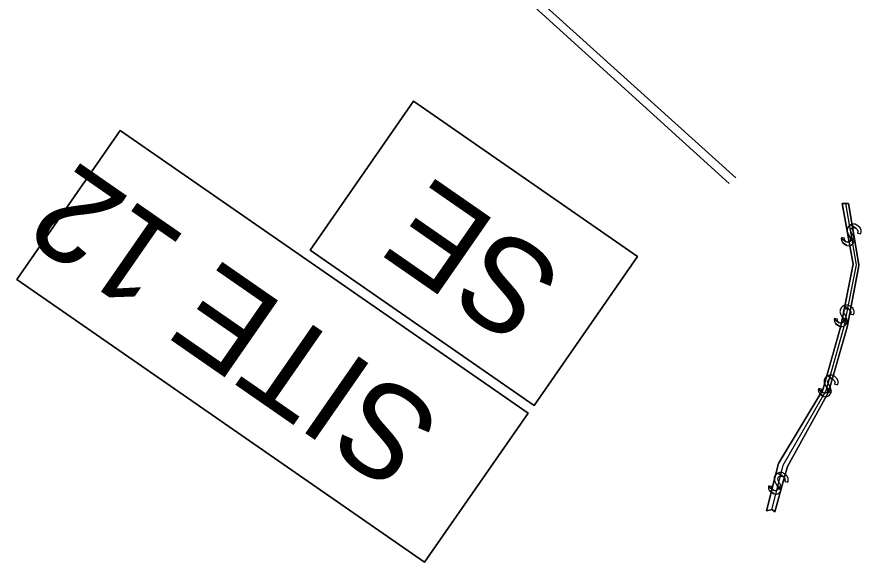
# Model space of a CAD drawing. Extents: x 474218 to 481634, y 484357 to 504997.
# Drawn here: x 478768.1 to 478903.4, y 494014.7 to 494102.1 of the extents above; entities that cross this region are included whole.
import ezdxf

# ---------------------------------------------------------------- set-up
doc = ezdxf.new("R2010")
doc.units = 0
for name, color, linetype in [('Exist Hydro Jurisdictional Stream or Body of Water', 7, 'Continuous'), ('Old_Level_29', 7, 'Continuous'), ('Prop Earthen Structure Impacts In Surface Waters Hatching CELL', 7, 'Continuous'), ('Prop Grid Mask', 7, 'Continuous'), ('Scratch_Level_4', 7, 'Continuous')]:
    doc.layers.add(name, color=color, linetype=linetype)

msp = doc.modelspace()

# ---------------------------------------------------------------- linework, layer by layer
at = {"layer": 'Exist Hydro Jurisdictional Stream or Body of Water'}
msp.add_lwpolyline([(478851.01, 494039.79), (478815.08, 494064.72), (478831.66, 494088.62), (478867.58, 494063.69)], close=True, dxfattribs=at)
at = {"layer": 'Old_Level_29'}
msp.add_lwpolyline([(478833.44, 494014.68), (478768.06, 494060.03), (478784.64, 494083.93), (478850.02, 494038.58)], close=True, dxfattribs=at)
at = {"layer": 'Prop Earthen Structure Impacts In Surface Waters Hatching CELL'}
msp.add_lwpolyline([(478891.05, 494028.01), (478891.61, 494030.01), (478896.76, 494039.31), (478898.21, 494041.94), (478901.18, 494052.35), (478902.99, 494061.94), (478903.07, 494062.35), (478901.38, 494072.23), (478900.38, 494072.2), (478902.14, 494062.49), (478900.19, 494052.51), (478897.28, 494042.33), (478890.17, 494030.48), (478889.63, 494028.39), (478888.23, 494022.9), (478889.16, 494023.1), (478889.57, 494022.72), (478891.05, 494028.01)], dxfattribs=at)
for points in [[(478902.37, 494068.33), (478902.58, 494068.24), (478901.77, 494068.8), (478901.73, 494068.78), (478901.72, 494068.78), (478901.71, 494068.77), (478901.64, 494068.74), (478901.62, 494068.72), (478901.6, 494068.71), (478901.52, 494068.64), (478901.49, 494068.6), (478901.46, 494068.58), (478901.36, 494068.49), (478901.33, 494068.41), (478901.23, 494068.24), (478901.19, 494068.16), (478901.18, 494068.08), (478901.17, 494067.93), (478901.17, 494067.93), (478901.16, 494067.81), (478901.19, 494067.7), (478901.27, 494067.44), (478901.31, 494067.36), (478901.47, 494067.05), (478901.56, 494066.9), (478902.34, 494066.36), (478902.32, 494066.46), (478902.28, 494066.69), (478902.25, 494066.76), (478902.11, 494067.06), (478902.03, 494067.2), (478901.91, 494067.41), (478901.78, 494067.67), (478901.76, 494067.76), (478901.74, 494067.88), (478901.8, 494068.08), (478901.85, 494068.15), (478901.94, 494068.25), (478901.98, 494068.27), (478902.02, 494068.29), (478902.12, 494068.34), (478902.16, 494068.34), (478902.21, 494068.34), (478902.34, 494068.34), (478902.36, 494068.34)], [(478903.25, 494068.31), (478902.89, 494068.65), (478902.44, 494068.87), (478902.44, 494068.87), (478902.04, 494068.89), (478901.99, 494068.89), (478901.77, 494068.8), (478902.58, 494068.24), (478902.77, 494068.05), (478902.77, 494068.05), (478902.78, 494068.03), (478902.85, 494067.9), (478902.88, 494067.85), (478902.88, 494067.82), (478902.9, 494067.68), (478902.9, 494067.63), (478902.89, 494067.59), (478902.86, 494067.45), (478903.17, 494067.4), (478903.25, 494067.38), (478903.35, 494067.37), (478903.38, 494067.47), (478903.39, 494067.49), (478903.4, 494067.52), (478903.42, 494067.59), (478903.42, 494067.6), (478903.42, 494067.61), (478903.42, 494067.65), (478903.42, 494067.9), (478903.41, 494067.93), (478903.25, 494068.31)], [(478902.22, 494065.94), (478902.28, 494066.05), (478901.74, 494066.43), (478901.73, 494066.28), (478901.63, 494066.11), (478901.62, 494066.1), (478901.58, 494066.07), (478901.47, 494065.99), (478901.4, 494065.99), (478901.31, 494065.98), (478901.27, 494065.97), (478901.24, 494065.98), (478901.16, 494066.02), (478901.04, 494066.06), (478900.24, 494066.61), (478900.23, 494066.55), (478900.26, 494066.31), (478900.27, 494066.26), (478900.43, 494065.96), (478901.15, 494065.46), (478901.45, 494065.44), (478901.53, 494065.44), (478901.73, 494065.51), (478901.8, 494065.53), (478901.84, 494065.54), (478901.86, 494065.55), (478901.87, 494065.56), (478901.89, 494065.57), (478901.94, 494065.61), (478901.97, 494065.64), (478902.07, 494065.73), (478902.11, 494065.76), (478902.12, 494065.77)], [(478900.77, 494066.48), (478900.76, 494066.64), (478900.48, 494066.68), (478900.39, 494066.69), (478900.26, 494066.71), (478900.25, 494066.68), (478900.25, 494066.67), (478900.25, 494066.64), (478900.24, 494066.61), (478901.04, 494066.06), (478900.86, 494066.22), (478900.84, 494066.26), (478900.84, 494066.27), (478900.82, 494066.32), (478900.77, 494066.42)], [(478901.11, 494065.48), (478901.15, 494065.46), (478900.43, 494065.96), (478900.44, 494065.95), (478900.76, 494065.65), (478900.76, 494065.65)], [(478902.32, 494066.28), (478902.34, 494066.36), (478901.56, 494066.9), (478901.66, 494066.74), (478901.74, 494066.5), (478901.74, 494066.43), (478902.29, 494066.05), (478902.3, 494066.11)], [(478901.24, 494055.35), (478901.45, 494055.26), (478900.64, 494055.82), (478900.6, 494055.8), (478900.6, 494055.8), (478900.59, 494055.8), (478900.51, 494055.76), (478900.49, 494055.75), (478900.47, 494055.73), (478900.39, 494055.66), (478900.36, 494055.63), (478900.34, 494055.6), (478900.24, 494055.51), (478900.2, 494055.44), (478900.1, 494055.26), (478900.06, 494055.18), (478900.05, 494055.1), (478900.04, 494054.95), (478900.04, 494054.95), (478900.03, 494054.83), (478900.06, 494054.72), (478900.14, 494054.46), (478900.18, 494054.39), (478900.34, 494054.07), (478900.44, 494053.92), (478901.21, 494053.38), (478901.19, 494053.49), (478901.15, 494053.71), (478901.12, 494053.78), (478900.98, 494054.09), (478900.9, 494054.22), (478900.79, 494054.43), (478900.65, 494054.69), (478900.63, 494054.79), (478900.61, 494054.91), (478900.67, 494055.11), (478900.72, 494055.17), (478900.81, 494055.27), (478900.85, 494055.29), (478900.89, 494055.31), (478901, 494055.37), (478901.04, 494055.37), (478901.09, 494055.36), (478901.22, 494055.36), (478901.23, 494055.36)], [(478902.12, 494055.34), (478901.77, 494055.67), (478901.31, 494055.89), (478901.31, 494055.89), (478900.91, 494055.91), (478900.86, 494055.91), (478900.64, 494055.82), (478901.45, 494055.26), (478901.64, 494055.08), (478901.65, 494055.07), (478901.65, 494055.05), (478901.73, 494054.92), (478901.75, 494054.87), (478901.76, 494054.84), (478901.77, 494054.71), (478901.77, 494054.65), (478901.76, 494054.61), (478901.73, 494054.48), (478902.04, 494054.42), (478902.12, 494054.41), (478902.22, 494054.39), (478902.25, 494054.49), (478902.26, 494054.52), (478902.27, 494054.54), (478902.29, 494054.61), (478902.29, 494054.63), (478902.29, 494054.63), (478902.29, 494054.67), (478902.29, 494054.92), (478902.29, 494054.95), (478902.12, 494055.33)], [(478901.09, 494052.96), (478901.16, 494053.07), (478900.61, 494053.45), (478900.6, 494053.3), (478900.5, 494053.13), (478900.49, 494053.12), (478900.45, 494053.09), (478900.34, 494053.02), (478900.27, 494053.01), (478900.18, 494053), (478900.14, 494053), (478900.11, 494053.01), (478900.03, 494053.04), (478899.92, 494053.08), (478899.11, 494053.63), (478899.1, 494053.57), (478899.13, 494053.33), (478899.14, 494053.28), (478899.3, 494052.98), (478900.02, 494052.49), (478900.32, 494052.46), (478900.4, 494052.46), (478900.6, 494052.53), (478900.67, 494052.55), (478900.71, 494052.56), (478900.74, 494052.57), (478900.74, 494052.58), (478900.76, 494052.6), (478900.81, 494052.64), (478900.84, 494052.66), (478900.94, 494052.75), (478900.98, 494052.78), (478900.99, 494052.79)], [(478899.64, 494053.5), (478899.63, 494053.66), (478899.35, 494053.7), (478899.26, 494053.71), (478899.13, 494053.73), (478899.13, 494053.7), (478899.12, 494053.69), (478899.12, 494053.67), (478899.11, 494053.63), (478899.92, 494053.08), (478899.73, 494053.24), (478899.71, 494053.28), (478899.71, 494053.3), (478899.69, 494053.34), (478899.64, 494053.45)], [(478901.19, 494053.3), (478901.21, 494053.38), (478900.44, 494053.92), (478900.53, 494053.76), (478900.61, 494053.52), (478900.61, 494053.45), (478901.16, 494053.07), (478901.17, 494053.13)], [(478899.98, 494052.51), (478900.02, 494052.49), (478899.3, 494052.98), (478899.31, 494052.97), (478899.63, 494052.67), (478899.63, 494052.67)], [(478898.69, 494044.11), (478898.89, 494044.02), (478898.08, 494044.58), (478898.04, 494044.56), (478898.04, 494044.56), (478898.03, 494044.56), (478897.95, 494044.52), (478897.93, 494044.51), (478897.92, 494044.49), (478897.84, 494044.42), (478897.81, 494044.39), (478897.78, 494044.36), (478897.68, 494044.27), (478897.64, 494044.2), (478897.54, 494044.02), (478897.5, 494043.94), (478897.5, 494043.86), (478897.48, 494043.71), (478897.48, 494043.71), (478897.47, 494043.59), (478897.5, 494043.48), (478897.58, 494043.22), (478897.62, 494043.15), (478897.79, 494042.83), (478897.88, 494042.68), (478898.65, 494042.14), (478898.63, 494042.25), (478898.59, 494042.47), (478898.56, 494042.54), (478898.42, 494042.85), (478898.35, 494042.98), (478898.23, 494043.19), (478898.09, 494043.45), (478898.08, 494043.55), (478898.05, 494043.67), (478898.11, 494043.87), (478898.17, 494043.93), (478898.26, 494044.03), (478898.29, 494044.05), (478898.34, 494044.07), (478898.44, 494044.13), (478898.48, 494044.12), (478898.53, 494044.12), (478898.66, 494044.12), (478898.68, 494044.12)], [(478899.56, 494044.1), (478899.21, 494044.43), (478898.76, 494044.65), (478898.75, 494044.65), (478898.35, 494044.67), (478898.31, 494044.67), (478898.08, 494044.58), (478898.89, 494044.02), (478899.09, 494043.84), (478899.09, 494043.83), (478899.1, 494043.81), (478899.17, 494043.68), (478899.2, 494043.63), (478899.2, 494043.6), (478899.21, 494043.47), (478899.21, 494043.41), (478899.21, 494043.37), (478899.17, 494043.24), (478899.48, 494043.18), (478899.56, 494043.17), (478899.67, 494043.15), (478899.7, 494043.25), (478899.7, 494043.28), (478899.71, 494043.3), (478899.73, 494043.37), (478899.73, 494043.38), (478899.73, 494043.39), (478899.73, 494043.43), (478899.73, 494043.68), (478899.73, 494043.71), (478899.57, 494044.09)], [(478898.64, 494042.06), (478898.65, 494042.14), (478897.88, 494042.68), (478897.98, 494042.52), (478898.06, 494042.28), (478898.05, 494042.21), (478898.6, 494041.83), (478898.61, 494041.89)], [(478898.53, 494041.72), (478898.6, 494041.83), (478898.05, 494042.21), (478898.04, 494042.06), (478897.94, 494041.89), (478897.93, 494041.88), (478897.89, 494041.85), (478897.78, 494041.78), (478897.71, 494041.77), (478897.62, 494041.76), (478897.58, 494041.76), (478897.56, 494041.77), (478897.47, 494041.8), (478897.36, 494041.84), (478896.56, 494042.39), (478896.55, 494042.33), (478896.58, 494042.09), (478896.58, 494042.04), (478896.74, 494041.74), (478897.46, 494041.25), (478897.76, 494041.22), (478897.84, 494041.22), (478898.05, 494041.29), (478898.12, 494041.31), (478898.15, 494041.32), (478898.18, 494041.33), (478898.19, 494041.34), (478898.21, 494041.36), (478898.25, 494041.4), (478898.29, 494041.42), (478898.39, 494041.51), (478898.42, 494041.54), (478898.43, 494041.55)], [(478897.08, 494042.26), (478897.07, 494042.42), (478896.8, 494042.46), (478896.7, 494042.47), (478896.57, 494042.49), (478896.57, 494042.46), (478896.57, 494042.45), (478896.56, 494042.43), (478896.56, 494042.39), (478897.36, 494041.84), (478897.17, 494042), (478897.16, 494042.04), (478897.15, 494042.06), (478897.13, 494042.1), (478897.09, 494042.21)], [(478897.42, 494041.27), (478897.46, 494041.25), (478896.74, 494041.74), (478896.75, 494041.73), (478897.07, 494041.43), (478897.07, 494041.43)], [(478890.7, 494028.48), (478890.9, 494028.39), (478890.09, 494028.95), (478890.05, 494028.93), (478890.05, 494028.93), (478890.04, 494028.93), (478889.96, 494028.9), (478889.94, 494028.88), (478889.92, 494028.86), (478889.85, 494028.79), (478889.81, 494028.76), (478889.79, 494028.73), (478889.69, 494028.64), (478889.65, 494028.57), (478889.55, 494028.39), (478889.51, 494028.31), (478889.5, 494028.24), (478889.49, 494028.08), (478889.49, 494028.08), (478889.48, 494027.96), (478889.51, 494027.85), (478889.59, 494027.59), (478889.63, 494027.52), (478889.8, 494027.2), (478889.89, 494027.05), (478890.66, 494026.51), (478890.64, 494026.62), (478890.6, 494026.84), (478890.57, 494026.91), (478890.43, 494027.22), (478890.35, 494027.35), (478890.24, 494027.56), (478890.1, 494027.82), (478890.08, 494027.92), (478890.06, 494028.04), (478890.12, 494028.24), (478890.18, 494028.3), (478890.27, 494028.4), (478890.3, 494028.42), (478890.35, 494028.44), (478890.45, 494028.5), (478890.49, 494028.5), (478890.54, 494028.49), (478890.67, 494028.49), (478890.68, 494028.49)], [(478891.57, 494028.47), (478891.22, 494028.8), (478890.76, 494029.03), (478890.76, 494029.03), (478890.36, 494029.04), (478890.31, 494029.04), (478890.09, 494028.95), (478890.9, 494028.39), (478891.09, 494028.21), (478891.1, 494028.2), (478891.11, 494028.19), (478891.18, 494028.05), (478891.2, 494028), (478891.21, 494027.97), (478891.22, 494027.84), (478891.22, 494027.78), (478891.21, 494027.74), (478891.18, 494027.61), (478891.49, 494027.55), (478891.57, 494027.54), (478891.67, 494027.52), (478891.71, 494027.62), (478891.71, 494027.65), (478891.72, 494027.67), (478891.74, 494027.74), (478891.74, 494027.76), (478891.74, 494027.76), (478891.74, 494027.8), (478891.74, 494028.05), (478891.74, 494028.08), (478891.58, 494028.46)], [(478890.54, 494026.09), (478890.61, 494026.2), (478890.06, 494026.58), (478890.05, 494026.43), (478889.95, 494026.26), (478889.94, 494026.25), (478889.9, 494026.22), (478889.79, 494026.15), (478889.72, 494026.14), (478889.63, 494026.13), (478889.59, 494026.13), (478889.56, 494026.14), (478889.48, 494026.17), (478889.37, 494026.21), (478888.57, 494026.76), (478888.56, 494026.7), (478888.59, 494026.47), (478888.59, 494026.41), (478888.75, 494026.11), (478889.47, 494025.62), (478889.77, 494025.6), (478889.85, 494025.59), (478890.06, 494025.66), (478890.13, 494025.68), (478890.16, 494025.69), (478890.19, 494025.7), (478890.19, 494025.71), (478890.22, 494025.73), (478890.26, 494025.77), (478890.3, 494025.79), (478890.4, 494025.88), (478890.43, 494025.91), (478890.44, 494025.92)], [(478889.09, 494026.63), (478889.08, 494026.79), (478888.8, 494026.83), (478888.71, 494026.84), (478888.58, 494026.86), (478888.58, 494026.83), (478888.58, 494026.82), (478888.57, 494026.8), (478888.57, 494026.76), (478889.37, 494026.21), (478889.18, 494026.37), (478889.16, 494026.41), (478889.16, 494026.43), (478889.14, 494026.47), (478889.09, 494026.58)], [(478890.65, 494026.43), (478890.66, 494026.51), (478889.89, 494027.05), (478889.98, 494026.89), (478890.07, 494026.65), (478890.06, 494026.58), (478890.61, 494026.2), (478890.62, 494026.26)], [(478889.43, 494025.64), (478889.47, 494025.62), (478888.75, 494026.11), (478888.76, 494026.1), (478889.08, 494025.8), (478889.08, 494025.8)]]:
    msp.add_lwpolyline(points, close=True, dxfattribs=at)
at = {"layer": 'Prop Grid Mask'}
for points in [[(478867.58, 494063.69), (478831.66, 494088.62), (478815.08, 494064.72), (478851.01, 494039.79)], [(478850.02, 494038.58), (478784.64, 494083.93), (478768.06, 494060.03), (478833.44, 494014.68)]]:
    msp.add_lwpolyline(points, close=True, dxfattribs=at)
at = {"layer": 'Scratch_Level_4'}
for p, q in [((478882.27, 494075.4), (478843.81, 494110.38)), ((478883.35, 494076.32), (478844.76, 494111.16))]:
    msp.add_line(p, q, dxfattribs=at)
msp.add_lwpolyline([(478889.57, 494022.72), (478889.16, 494023.1), (478888.23, 494022.9), (478889.63, 494028.39), (478890.17, 494030.48), (478897.28, 494042.33), (478900.19, 494052.51), (478902.14, 494062.49), (478900.38, 494072.2), (478901.38, 494072.23), (478903.07, 494062.35), (478902.99, 494061.94), (478901.18, 494052.35), (478898.21, 494041.94), (478896.76, 494039.31), (478891.61, 494030.01), (478891.05, 494028.01)], close=True, dxfattribs=at)
msp.add_lwpolyline([(478900.92, 494072.22), (478902.62, 494062.39), (478900.67, 494052.41), (478897.75, 494042.16), (478890.87, 494030.18), (478889.05, 494023.07)], dxfattribs=at)

# ---------------------------------------------------------------- texts
at = {"layer": 'Exist Hydro Jurisdictional Stream or Body of Water'}
msp.add_text('SE', height=15, rotation=145.252, dxfattribs=at).set_placement((478856.4, 494061.39))
at = {"layer": 'Old_Level_29'}
msp.add_text('SITE 12', height=15, rotation=145.252, dxfattribs=at).set_placement((478836.91, 494037.93))

doc.saveas('drawing.dxf')
